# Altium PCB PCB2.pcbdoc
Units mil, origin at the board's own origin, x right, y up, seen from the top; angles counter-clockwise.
Board outline 3520 x 2895 mil, 2 copper layers (Top Layer, Bottom Layer), stack 62.2 mil thick; 16 components, 24 nets, 134 pads, 52 vias.
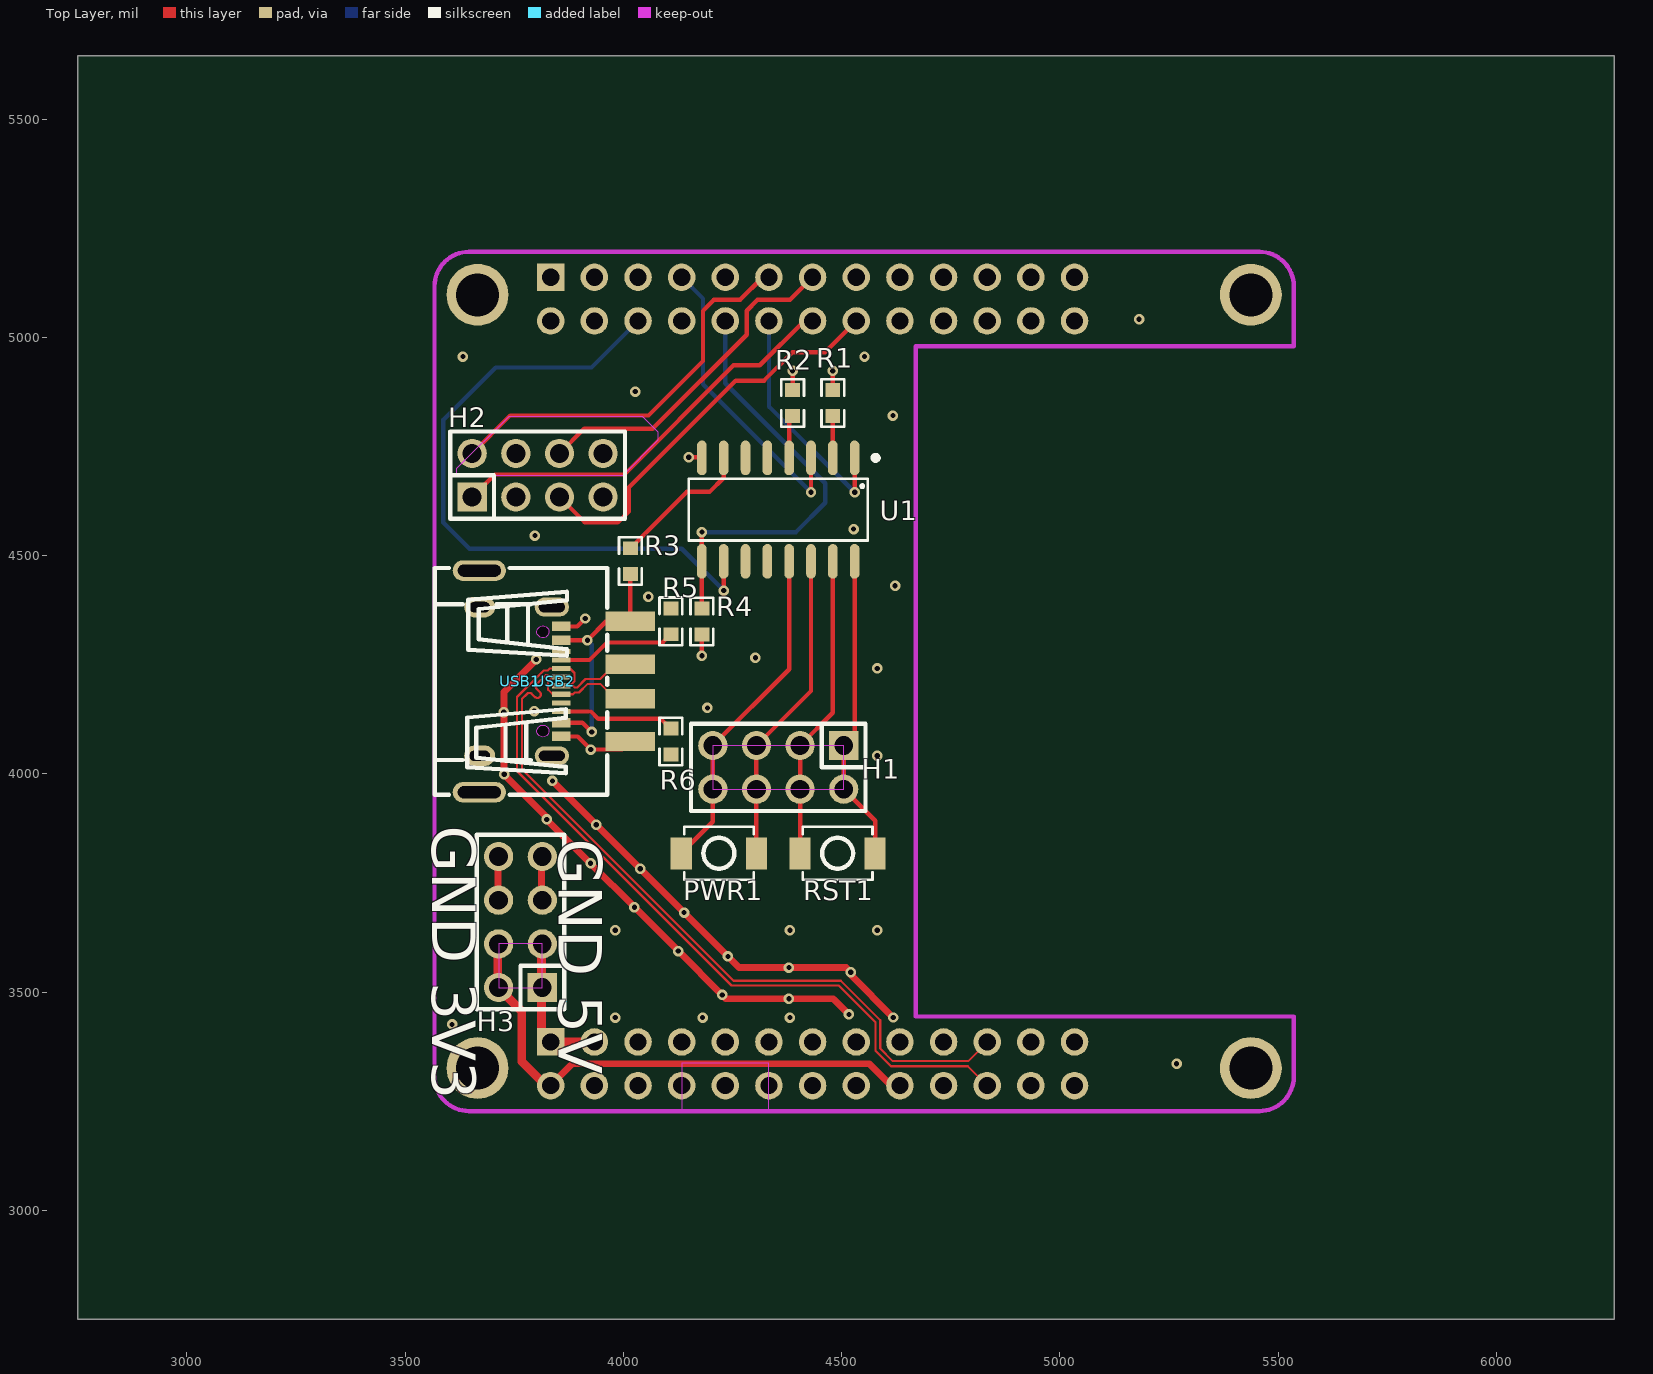
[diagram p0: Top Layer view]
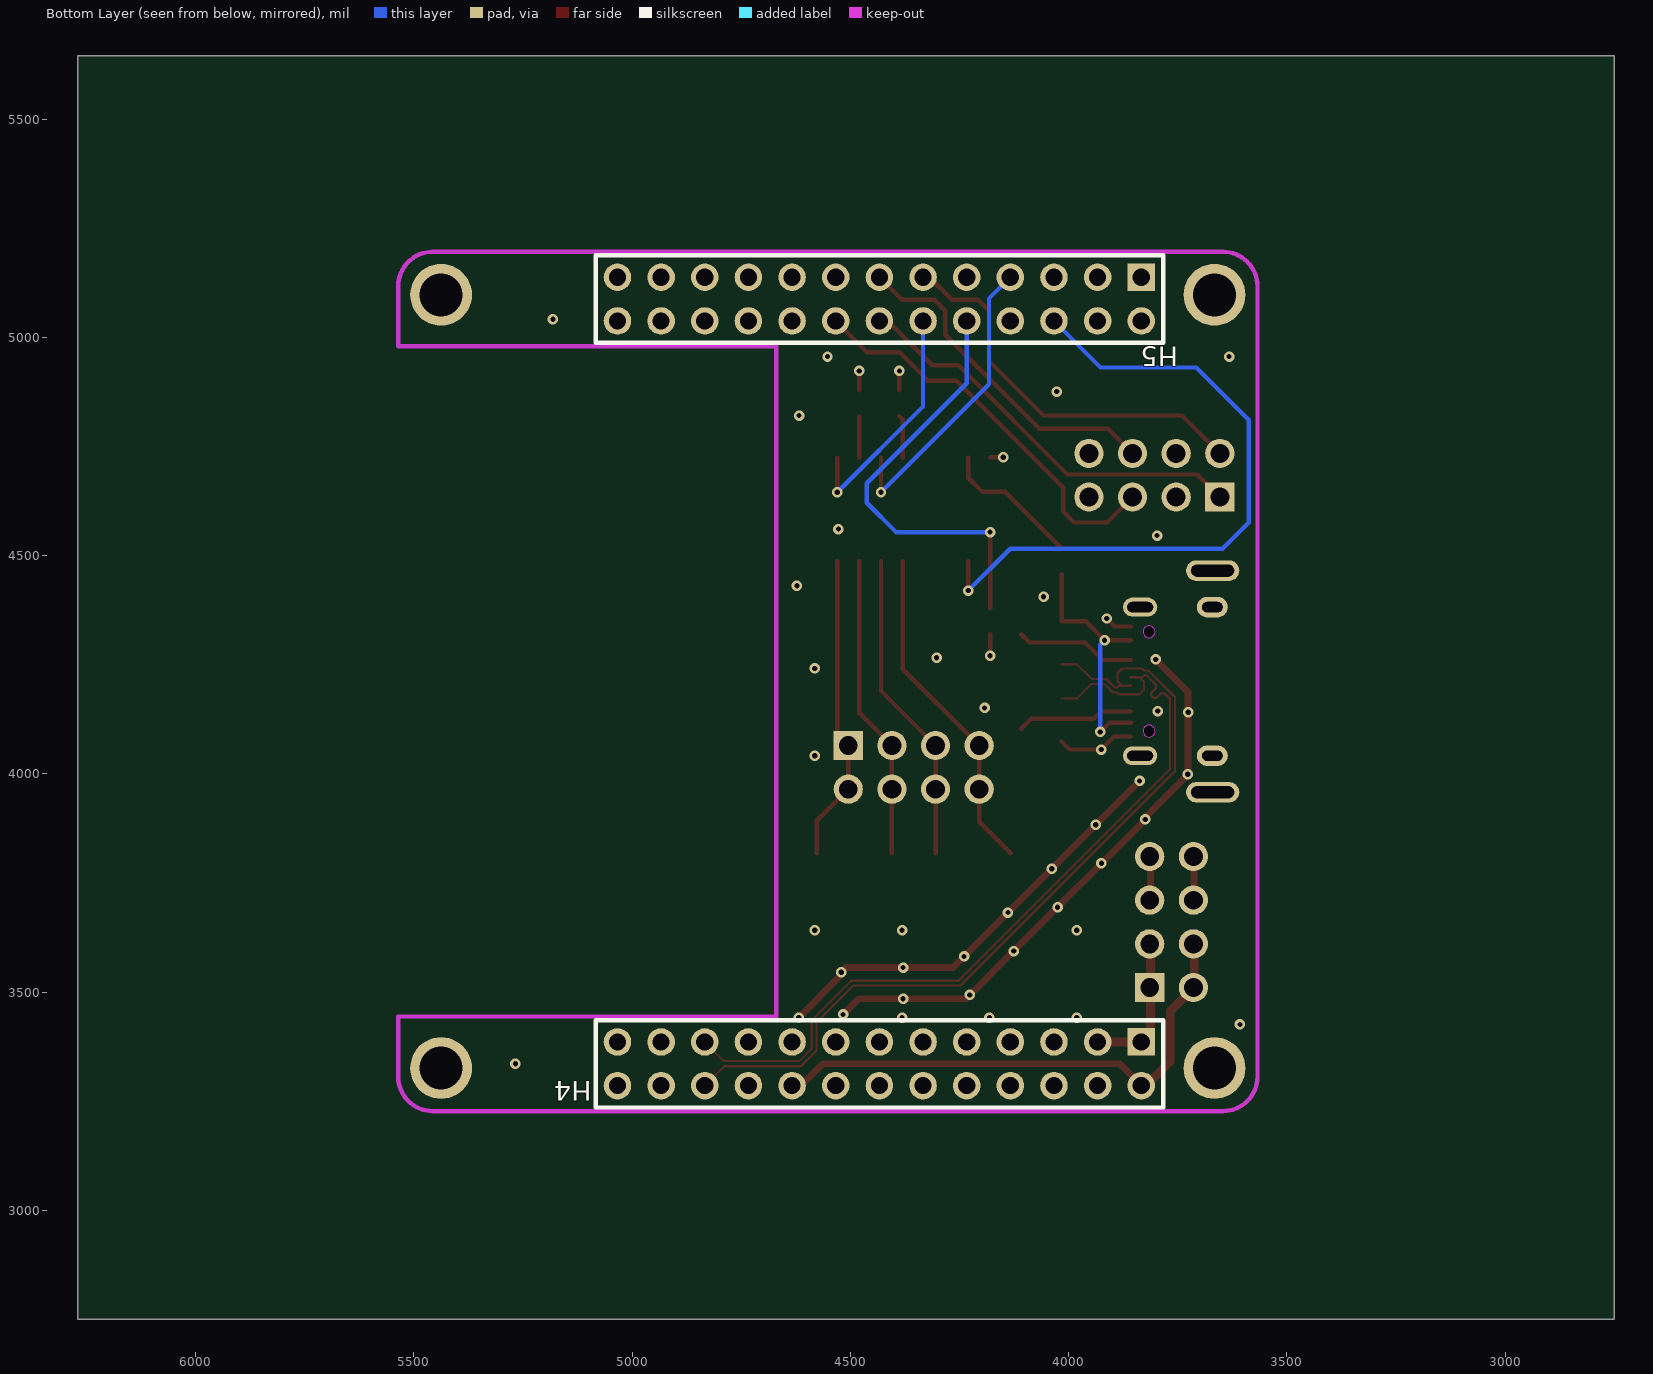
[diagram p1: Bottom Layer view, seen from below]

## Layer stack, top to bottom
Top Solder Mask Layer: solder mask 0.4, Dk 3.3
Top Layer: signal copper 1.4
Dielectric1: surface 59.4, FR4, Dk 4.5
Bottom Layer: signal copper 1.4
Bottom Solder Mask Layer: solder mask 0.4, Dk 3.3

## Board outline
6270,2750 2750,2750 2750,5645 6270,5645

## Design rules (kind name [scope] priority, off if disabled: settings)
BoardOutlineClearance copperThickness1oz [All] p0: genericclearance=10 ignorepadtopadclearanceinfootprint=FALSE except(0: Arc-SplitContinuation Track-SplitContinuation SMDPad-SplitContinuation THPad-SplitContinuation Via-SplitContinuation Fill-SplitContinuation Poly-SplitContinuation Region-SplitContinuation Text-SplitContinuation)
BoardOutlineClearance copperThickness2oz [All] p0: genericclearance=10 ignorepadtopadclearanceinfootprint=FALSE except(0: Arc-SplitContinuation Track-SplitContinuation SMDPad-SplitContinuation THPad-SplitContinuation Via-SplitContinuation Fill-SplitContinuation Poly-SplitContinuation Region-SplitContinuation Text-SplitContinuation)
BoardOutlineClearance otherClearance [All] p0: genericclearance=10 ignorepadtopadclearanceinfootprint=FALSE except(0: Arc-SplitContinuation Track-SplitContinuation SMDPad-SplitContinuation THPad-SplitContinuation Via-SplitContinuation Fill-SplitContinuation Poly-SplitContinuation Region-SplitContinuation Text-SplitContinuation)
Clearance copperThickness1oz [All] p1: gap=7 ignorepadtopadclearanceinfootprint=FALSE
Clearance copperThickness2oz [All] p1: gap=7 ignorepadtopadclearanceinfootprint=FALSE
Clearance otherClearance [All] p1: gap=7 ignorepadtopadclearanceinfootprint=FALSE
DiffPairsRouting differentialPair [All] p1: maxuncoupledlength=10 minlimit=6 maxlimit=Infinity mostfreqgap=6 toplayer_minwidth=5 toplayer_prefwidth=10 toplayer_maxwidth=100 bottomlayer_minwidth=5 bottomlayer_prefwidth=10 bottomlayer_maxwidth=100
PasteMaskExpansion pasteMaskExpansion [All] p1: expansion=0
PlaneConnect innerPlane [All] p1: planeconnectstyle=Relief reliefexpansion=20 reliefentries=4 reliefconductorwidth=10 reliefairgap=10
PolygonConnect copperRegion [All] p1: connectstyle=Direct reliefentries=4 reliefconductorwidth=10 polygonreliefangle="90 Angle" airgapwidth=10
PolygonConnect copperRegion1 [All] p1: connectstyle=Direct reliefentries=4 reliefconductorwidth=10 polygonreliefangle="90 Angle" airgapwidth=10
RoutingVias viaSize [All] p1: viastyle="Through Hole" holewidth=12.0078 minholewidth=11.811 maxholewidth=248.0314 width=12.0078 minwidth=11.811 maxwidth=248.0314
SolderMaskExpansion solderMaskExpansion [IsVia] p1: useseparateexpansions=TRUE expansion=-1000 expansionbottom=-1000
SolderMaskExpansion solderMaskExpansion [All] p2: useseparateexpansions=TRUE expansion=2 expansionbottom=2
Width copperThickness1oz [All] p1: maxlimit=100 minlimit=5 preferedwidth=10
Width copperThickness2oz [All] p1: maxlimit=100 minlimit=8 preferedwidth=10

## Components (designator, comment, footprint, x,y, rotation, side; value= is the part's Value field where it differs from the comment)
H1 "PZ2.54-2*4" HDR-TH_8P-P2.54-V-M-R2-C4-S2.54 4354.8,4014.7 r180 top
H2 "PZ2.54-2*4" HDR-TH_8P-P2.54-V-M-R2-C4-S2.54 3803.6,4684.1 r0 top
H3 "PZ2.54-2*4" HDR-TH_8P-P2.54-V-M-R2-C4-S2.54 3764.2,3660.4 r90 top
H4 "X5521FV-2x13-C70D30-1000" HDR-TH_26P-P2.54-V-F-R2-C13-S2.54-3 4433.5,3335.6 r0 bottom
H5 "X5521FV-2x13-C70D30-1000" HDR-TH_26P-P2.54-V-F-R2-C13-S2.54-3 4433.5,5087.6 r0 bottom
PWR1 "TS-1088-AR02016" SW-SMD_L3.9-W3.0-P4.45#1 4218.8,3817.9 r180 top
R1 "470Ω" R0603#1 4479.8,4849.4 r270 top
R2 "470Ω" R0603#1 4387.7,4849.4 r270 top
R3 "2.2kΩ" R0603#2 4016,4487.2 r270 top
R4 "10kΩ" R0603#3 4179.8,4349.1 r90 top
R5 "5.1kΩ" R0603#1 4108.7,4349.4 r270 top
R6 "5.1kΩ" R0603#1 4108.7,4073.8 r90 top
RST1 "TS-1088-AR02016" SW-SMD_L3.9-W3.0-P4.45#2 4490.8,3817.9 r180 top
U1 "AQS221R2S" SO-16_L10.3-W4.4-P1.27-LS7.0-BL 4354.8,4605.3 r180 top
USB1 "TYPE-C 16PIN 2MD(073)" USB-C-SMD_TYPE-C-16PIN-2MD-073 3764.2,4211.6 r270 top
USB2 "10.0 QHHTZB6.3" USB-A-TH_10.0QHHTZB6.3 3843,4211.6 r270 top

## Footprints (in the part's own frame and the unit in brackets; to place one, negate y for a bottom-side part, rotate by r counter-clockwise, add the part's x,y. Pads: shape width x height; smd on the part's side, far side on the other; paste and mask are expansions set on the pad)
HDR-TH_8P-P2.54-V-M-R2-C4-S2.54 [mil]
  rect 66.9x66.9 hole 43.3: 1(-150,-50)
  round 66.9 hole 43.3: 2(-150,50) 3(-50,-50) 4(-50,50) 5(50,-50) 6(50,50) 7(150,-50) 8(150,50)
  silkscreen extent -200,-100 200,100
HDR-TH_26P-P2.54-V-F-R2-C13-S2.54-3 [mil]
  rect 63x63 hole 39.4: 1(-600,-50)
  round 63 hole 39.4: 2(-600,50) 3(-500,-50) 4(-500,50) 5(-400,-50) 6(-400,50) 7(-300,-50) 8(-300,50) 9(-200,-50) 10(-200,50) 11(-100,-50) 12(-100,50) 13(0,-50) 14(0,50) 15(100,-50) 16(100,50) 17(200,-50) 18(200,50) 19(300,-50) 20(300,50) 21(400,-50) 22(400,50) 23(500,-50) 24(500,50) 25(600,-50) 26(600,50)
  silkscreen extent -650,-100 650,100
R0603#1 [mil]
  rect 31.8x34 smd paste-3937 mask+2: 1(-29.7,0) 2(29.7,0)
  silkscreen extent -55,-26 55,26
R0603#2 [mil]
  rect 31.8x34 smd paste-3937 mask+2: 1(-29.6,0) 2(29.7,0)
  silkscreen extent -55,-26 55,26
R0603#3 [mil]
  rect 31.8x34 smd paste-3937 mask+2: 1(-29.7,0) 2(29.6,0)
  silkscreen extent -54,-26 54,26
SO-16_L10.3-W4.4-P1.27-LS7.0-BL [mil]
  oval 22x79.5 smd: 1(-175,-118.5) 2(-125,-118.5) 3(-75,-118.5) 4(-25,-118.5) 5(25,-118.5) 6(75,-118.5) 7(125,-118.5) 8(175,-118.5) 9(175,118.5) 10(125,118.5) 11(75,118.5) 12(25,118.5) 13(-25,118.5) 14(-75,118.5) 15(-125,118.5) 16(-175,118.5)
  silkscreen extent -227,-122 205,71
SW-SMD_L3.9-W3.0-P4.45#1 [mil]
  rect 48.4x73.2 smd: 1(-86,0) 2(86.1,0)
  silkscreen extent -80,-61 80,61
SW-SMD_L3.9-W3.0-P4.45#2 [mil]
  rect 48.4x73.2 smd: 1(-86,0) 2(86,0)
  silkscreen extent -80,-61 80,61
USB-A-TH_10.0QHHTZB6.3 [mil]
  rect 44.1x113.4 smd paste-3937 mask+2: 1(-137.8,173) 2(-39.4,173) 3(39.4,173) 4(137.8,173)
  oval 47.2x122 hole 27.6 slot 98.4 at 90 deg: 5(-253.9,-173) 6(253.9,-173)
  silkscreen extent -260,-275 260,120
USB-C-SMD_TYPE-C-16PIN-2MD-073 [mil]
  oval 43.3x78.7 hole 23.6 slot 59.1 at 90 deg paste+0 mask+2: 13(-170.3,71.9) 14(170.3,71.9)
  oval 47.2x70.9 hole 23.6 slot 47.2 at 90 deg paste+0 mask+2: 13(-170.3,-93.5) 14(170.3,-93.5)
  rect 21.7x43.3 smd paste-3937 mask+2: A1B12(-126,93.5) A4B9(-94.5,93.5) B1A12(126,93.5) B4A9(94.5,93.5)
  rect 11.8x43.3 smd paste-3937 mask+2: A5(-49.2,93.5) A6(-9.8,93.5) A7(9.8,93.5) A8(49.2,93.5) B5(68.9,93.5) B6(29.5,93.5) B7(-29.5,93.5) B8(-68.9,93.5)
  Board Outline Layer lines w0.1: 113,37.7 116.2,37.8 119.2,38.8 122,40.4 124.3,42.6 126.1,45.2 127.2,48.2 127.6,51.4 127.2,54.6 126.1,57.6 124.3,60.3 122,62.5 119.2,64.1 116.2,65 113,65.2 109.8,64.6 106.9,63.4 104.3,61.4 102.3,59 100.8,56.1 100.1,53 100.1,49.8 100.8,46.7 102.3,43.8 104.3,41.4 106.9,39.5 109.8,38.2 113,37.7 ; -114.6,37.7 -111.4,37.8 -108.3,38.8 -105.5,40.4 -103.2,42.6 -101.5,45.2 -100.4,48.2 -100,51.4 -100.4,54.6 -101.5,57.6 -103.2,60.3 -105.5,62.5 -108.3,64.1 -111.4,65 -114.6,65.2 -117.7,64.6 -120.7,63.4 -123.2,61.4 -125.3,59 -126.7,56.1 -127.5,53 -127.5,49.8 -126.7,46.7 -125.3,43.8 -123.2,41.4 -120.7,39.5 -117.7,38.2 -114.6,37.7
  Board Outline Layer region: -100,51.4 -100.4,48.2 -101.5,45.2 -103.2,42.6 -105.5,40.4 -108.3,38.8 -111.4,37.8 -114.6,37.7 -117.7,38.2 -120.7,39.5 -123.2,41.4 -125.3,43.8 -126.7,46.7 -127.5,49.8 -127.5,53 -126.7,56.1 -125.3,59 -123.2,61.4 -120.7,63.4 -117.7,64.6 -114.6,65.2 -111.4,65 -108.3,64.1 -105.5,62.5 -103.2,60.3 -101.5,57.6 -100.4,54.6
  Board Outline Layer region: -100,51.4 -100.4,48.2 -101.5,45.2 -103.2,42.6 -105.5,40.4 -108.3,38.8 -111.4,37.8 -114.6,37.7 -117.7,38.2 -120.7,39.5 -123.2,41.4 -125.3,43.8 -126.7,46.7 -127.5,49.8 -127.5,53 -126.7,56.1 -125.3,59 -123.2,61.4 -120.7,63.4 -117.7,64.6 -114.6,65.2 -111.4,65 -108.3,64.1 -105.5,62.5 -103.2,60.3 -101.5,57.6 -100.4,54.6
  Board Outline Layer region: 127.6,51.4 127.2,48.2 126.1,45.2 124.3,42.6 122,40.4 119.2,38.8 116.2,37.8 113,37.7 109.8,38.2 106.9,39.5 104.3,41.4 102.3,43.8 100.8,46.7 100.1,49.8 100.1,53 100.8,56.1 102.3,59 104.3,61.4 106.9,63.4 109.8,64.6 113,65.2 116.2,65 119.2,64.1 122,62.5 124.3,60.3 126.1,57.6 127.2,54.6
  Board Outline Layer region: 127.6,51.4 127.2,48.2 126.1,45.2 124.3,42.6 122,40.4 119.2,38.8 116.2,37.8 113,37.7 109.8,38.2 106.9,39.5 104.3,41.4 102.3,43.8 100.8,46.7 100.1,49.8 100.1,53 100.8,56.1 102.3,59 104.3,61.4 106.9,63.4 109.8,64.6 113,65.2 116.2,65 119.2,64.1 122,62.5 124.3,60.3 126.1,57.6 127.2,54.6
  Multi-Layer board cut-out: -100,51.4 -100.4,48.2 -101.5,45.2 -103.2,42.6 -105.5,40.4 -108.3,38.8 -111.4,37.8 -114.6,37.7 -117.7,38.2 -120.7,39.5 -123.2,41.4 -125.3,43.8 -126.7,46.7 -127.5,49.8 -127.5,53 -126.7,56.1 -125.3,59 -123.2,61.4 -120.7,63.4 -117.7,64.6 -114.6,65.2 -111.4,65 -108.3,64.1 -105.5,62.5 -103.2,60.3 -101.5,57.6 -100.4,54.6
  Multi-Layer board cut-out: 127.6,51.4 127.2,48.2 126.1,45.2 124.3,42.6 122,40.4 119.2,38.8 116.2,37.8 113,37.7 109.8,38.2 106.9,39.5 104.3,41.4 102.3,43.8 100.8,46.7 100.1,49.8 100.1,53 100.8,56.1 102.3,59 104.3,61.4 106.9,63.4 109.8,64.6 113,65.2 116.2,65 119.2,64.1 122,62.5 124.3,60.3 126.1,57.6 127.2,54.6
  silkscreen extent -177,-196 180,24

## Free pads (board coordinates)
  round 141.7 hole 98.4: 1(3665.8,3325.8) 1(3665.8,5097.4) 1(5437.5,3325.8) 1(5437.5,5097.4)

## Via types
v1: diameter 24, hole 12, Top Layer to Bottom Layer, 52 vias

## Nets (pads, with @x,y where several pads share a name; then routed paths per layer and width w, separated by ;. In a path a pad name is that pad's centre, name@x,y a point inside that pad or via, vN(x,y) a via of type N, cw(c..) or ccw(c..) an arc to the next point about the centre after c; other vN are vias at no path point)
3V3_SYS: H5.6 U1.10 | length 1549.1
  Top Layer w10: v1(4229.8,4419.8) U1.10
  Bottom Layer w10: H5.6 3926.8,4930.8 3707.4,4930.8 3587.4,4810.8 3587.4,4575.8 3647.4,4515.8 4133.7,4515.8 v1(4229.8,4419.8)
3V3_SYS_B: H3.2 H3.4 H4.2 H4.18 | length 1228.3
  Top Layer w15.7: H4.2 3883.8,3335.8 4562.4,3335.8 4612.6,3285.6 H4.18
  Top Layer w20: H3.4@3712.4,3615.8 3712.4,3510.8 3767.4,3455.8 3767.4,3340.8 3822.6,3285.6 H4.2
5V_SYS: H5.2
5V_SYS_B: H3.1 H3.3 H4.1 H4.3 | length 338.9
  Top Layer w20: H3.3@3812.4,3615.8 3812.4,3515.8 3812.4,3406.8 H4.1 H4.3
$1N44: R3.1 U1.7 | length 326.3
  Top Layer w10: R3.1 4145,4645.8 4197.4,4645.8 4229.8,4678.2 U1.7
$1N61: R2.2 U1.4 | length 99.2
  Top Layer w10: U1.4 4379.8,4811.9 R2.2
$1N64: R1.2 U1.2 | length 95.9
  Top Layer w10: U1.2 R1.2
$1N142: R6.2 USB1.B5 | length 267.2
  Top Layer w10: USB1.B5 3925.5,4142.7 3942.4,4125.8 4086.3,4125.8 R6.2
$1N144: R5.2 USB1.A5 | length 275.4
  Top Layer w10: USB1.A5 3922.3,4260.8 3962.4,4300.8 4089.8,4300.8 R5.2
D+: H4.21 USB1.A6 USB1.B6 USB2.3 | length 1962.3
  Top Layer w5: 3779,4183 3767.4,4171.4 3767.4,4010.8 4252.4,3525.8 4497.9,3525.8 4588.4,3435.4 4588.4,3370.8 4617.4,3341.8 4789.8,3341.8 H4.21 ; 3779.04,4183.06 cw(c3784.7,4177.4) 3790.36,4183.06 ; 3790.3,4183 3797.2,4176.1 ; 3797.24,4176.04 ccw(c3802.9,4181.7) 3808.56,4187.36 ; 3801.6,4194.3 3808.6,4187.4 ; 3801.6,4205.7 3821.8,4225.8 3826.8,4225.8 3831.1,4221.4 USB1.A6@3837.9,4221.4 ; 3801.64,4194.34 cw(c3807.3,4200) 3801.64,4205.66 ; USB1.A6 USB1.A6@3837.9,4221.4 ; USB2.3 3981,4172.2 3947.1,4206.1 3918,4206.1 3898.3,4186.4 3888.7,4186.4 3884.4,4182.1 USB1.B6 3837.9,4182.1 3827.6,4192.3 3827.6,4211.2 USB1.A6@3837.9,4221.4
D-: H4.22 USB1.A7 USB1.B7 USB2.2 | length 1961.8
  Top Layer w5: USB1.A7 USB1.A7@3877.6,4201.8 ; USB2.2 3981,4251 3947.1,4217.1 3913.4,4217.1 3893.7,4197.4 3888.7,4197.4 3884.4,4201.8 USB1.A7@3877.6,4201.8 ; H4.22 4789,3330.1 4613.1,3330.1 4577.4,3365.8 4577.4,3430.8 4493.4,3514.8 4247.8,3514.8 3756.4,4006.3 3756.4,4176 3817.2,4236.8 3826.8,4236.8 3831.1,4241.1 USB1.B7 3877.6,4241.1 3887.9,4230.9 3887.9,4212 USB1.A7@3877.6,4201.8
GND: H2.3 H2.4 H2.7 H2.8 H3.5 H3.6 H3.7 H3.8 H4.5 H4.10 H4.13 H4.19 H4.26 H5.3 H5.4 H5.8 H5.9 H5.17 H5.25 H5.26 R1.1 R2.1 R4.1 R5.1 R6.1 U1.8 USB1.A1B12 USB1.B1A12 USB2.4 | length 2932.8
  Top Layer w10: USB1.B1A12 3895.4,4085.6 v1(3925.4,4055.6) 3997.8,4055.6 USB2.4 ; USB1.A1B12 3894.1,4337.6 v1(3912.4,4355.8) ; v1(4149.8,4725.1) 4178.5,4725.1 U1.8 ; v1(4179.8,4270.3) R4.1 ; R2.1 v1(4387.7,4923.1) ; R1.1 v1(4479.8,4923.1)
  Top Layer w15.7: H3.6@3712.4,3715.8 H3.8@3712.4,3815.8 ; v1(3800.6,4262.1) 3726.1,4187.6 v1(3726.1,4141.1) 3726.1,3999.9 v1(3727,3998.9) 3824.4,3901.5 v1(3824.4,3895.4) v1(3924.9,3794.9) v1(4025.4,3694.5) v1(4125.9,3594) v1(4226.4,3493.5) 4235.3,3484.6 v1(4379.2,3484.6) 4480.9,3484.6 v1(4516.8,3448.7) ; H3.5@3812.4,3715.8 H3.7@3812.4,3815.8 ; v1(3837.5,3983.6) v1(3938,3883.1) v1(4038.5,3782.6) v1(4139,3682.1) v1(4239.4,3581.6) 4264.9,3556.1 v1(4379.3,3556.1) 4510.5,3556.1 v1(4521,3545.6) 4521,3538.7 v1(4618,3441.7)
  other v1: 5267.4,3335.8 3607.4,3425.8 3981.5,3441.4 4181.5,3441.4 4381.5,3441.4 3981.5,3641.4 4381.5,3641.4 4581.5,3641.4 4581.5,4041.4 3795.8,4143.8 4192.4,4150.8 4581.5,4241.4 4302.4,4265.8 4057.4,4405.8 4622.4,4430.8 3797.4,4545.8 4527.4,4560.8 4617.4,4820.8 4027.4,4875.8 3632.4,4955.8 4552.4,4955.8 5181.5,5041.4
GPIO6: H2.2 H5.11 | length 914.4
  Top Layer w10: H2.2 3740.4,4820.8 4057.4,4820.8 4182.4,4945.8 4182.4,5060.8 4207.4,5085.8 4267.4,5085.8 4319.1,5137.6 H5.11
GPIO47: H2.5 H5.16 | length 927.6
  Top Layer w10: H2.5 3911.8,4575.8 3987.4,4575.8 4012.4,4600.8 4012.4,4655.8 4257.4,4900.8 4322.4,4900.8 4387.4,4965.8 4461.8,4965.8 H5.16
GPIO53: H2.6 H5.13 | length 779.3
  Top Layer w10: H2.6 3910.4,4790.8 4067.4,4790.8 4282.4,5005.8 4282.4,5060.8 4307.4,5085.8 4381.8,5085.8 H5.13
GPIO54: H2.1 H5.14 | length 947
  Top Layer w10: H2.1 3705.4,4685.8 4002.4,4685.8 4252.4,4935.8 4312.4,4935.8 4414.1,5037.6 H5.14
IO_PWR: H5.7 U1.3 | length 693.9
  Top Layer w10: v1(4429.8,4645.1) U1.3
  Bottom Layer w10: H5.7 4182.4,5088.7 4182.4,4892.5 v1(4429.8,4645.1)
IO_RST: H5.12 U1.1 | length 552.5
  Top Layer w10: v1(4529.8,4645.1) U1.1
  Bottom Layer w10: H5.12 4333.5,4841.3 v1(4529.8,4645.1)
PWR_DET: H5.10 R4.2 U1.9 | length 997
  Top Layer w10: R4.2@4179.8,4378.8 U1.9 v1(4179.8,4553.8)
  Bottom Layer w10: v1(4179.8,4553.8) 4395.4,4553.8 4462.4,4620.8 4462.4,4665.8 4233.5,4894.7 H5.10
PWR_SW1: H1.7 H1.8 PWR1.2 U1.13 | length 771.3
  Top Layer w10: PWR1.2 4204.8,3889.9 H1.8 H1.7 4379.8,4239.7 U1.13
PWR_SW2: H1.5 H1.6 PWR1.1 U1.14 | length 720.7
  Top Layer w10: PWR1.1 H1.6 H1.5 4429.8,4189.7 U1.14
RST_SW1: H1.3 H1.4 RST1.2 U1.15 | length 700
  Top Layer w10: RST1.2 H1.4 H1.3 4479.8,4139.7 U1.15
RST_SW2: H1.1 H1.2 RST1.1 U1.16 | length 709.1
  Top Layer w10: U1.16 4529.8,4089.7 H1.1 H1.2 4576.8,3892.7 RST1.1
USB5V: R3.2 USB1.A4B9 USB1.B4A9 USB2.1 | length 577.2
  Top Layer w10: USB1.B4A9 3906.1,4117.1 v1(3927.4,4095.8) ; USB1.A4B9 v1(3917.6,4306.1) 3960.9,4349.4 USB2.1 R3.2
  Bottom Layer w10: v1(3917.6,4306.1) 3927.4,4296.3 v1(3927.4,4095.8)
pads on no net: H4.4 H4.6 H4.7 H4.8 H4.9 H4.11 H4.12 H4.14 H4.15 H4.16 H4.17 H4.20 H4.23 H4.24 H4.25 H5.1 H5.5 H5.15 H5.18 H5.19 H5.20 H5.21 H5.22 H5.23 H5.24 U1.5 U1.6 U1.11 U1.12 USB1.13 USB1.14 USB1.A8 USB1.B8 USB2.5 USB2.6

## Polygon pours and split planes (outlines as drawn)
GND on Top Layer (solid, remove dead copper, pour order 2): 3215,5395 3215,3010 6020,3010 6020,5395
GND on Bottom Layer (solid, remove dead copper, pour order 2): 3000,5385 3000,3000 5805,3000 5805,5385

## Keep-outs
Top Layer:
  region: 4204.8,4064.7 4204.8,3964.7 4504.8,3964.7 4504.8,4064.7
  region: 4133.5,3336.5 4133.5,3230.6 4333.5,3230.6 4333.5,3336.5
  region: 3714.2,3610.4 3714.2,3510.4 3814.2,3510.4 3814.2,3610.4
  region: 3618.6,4683.4 3618.6,4699.7 3738,4819.1 4043.6,4819.1 4078.9,4783.7 4078.9,4763.7 3998.6,4683.4
Board Outline Layer:
  lines w10: 3567.4,3306.1 3567.4,5117.1 3567.8,5124.8 3568.9,5132.5 3570.8,5140 3573.4,5147.2 3576.7,5154.2 3580.7,5160.9 3585.3,5167.1 3590.5,5172.8 3596.2,5178 3602.4,5182.6 3609,5186.6 3616,5189.9 3623.3,5192.5 3630.8,5194.3 3638.4,5195.5 3646.1,5195.8 5457.2,5195.8 5464.9,5195.5 5472.5,5194.3 5480,5192.5 5487.3,5189.9 5494.3,5186.6 5500.9,5182.6 5507.1,5178 5512.8,5172.8 5518,5167.1 5522.6,5160.9 5526.6,5154.2 5529.9,5147.2 5532.5,5140 5534.4,5132.5 5535.5,5124.8 5535.9,5117.1 5535.9,4979.3 4669.8,4979.3 4669.8,3443.9 5535.9,3443.9 5535.9,3306.1 5535.5,3298.4 5534.4,3290.7 5532.5,3283.2 5529.9,3276 5526.6,3269 5522.6,3262.3 5518,3256.1 5512.8,3250.4 5507.1,3245.2 5500.9,3240.6 5494.3,3236.6 5487.3,3233.3 5480,3230.7 5472.5,3228.9 5464.9,3227.7 5457.2,3227.3 3646.1,3227.3 3638.4,3227.7 3630.8,3228.9 3623.3,3230.7 3616,3233.3 3609,3236.6 3602.4,3240.6 3596.2,3245.2 3590.5,3250.4 3585.3,3256.1 3580.7,3262.3 3576.7,3269 3573.4,3276 3570.8,3283.2 3568.9,3290.7 3567.8,3298.4 3567.4,3306.1

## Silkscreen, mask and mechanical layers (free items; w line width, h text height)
Top Silkscreen Layer:
  text "GND 3V3" at 3562.4,3880.8 h100 r270
  text "GND 5V" at 3852.4,3850.8 h100 r270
